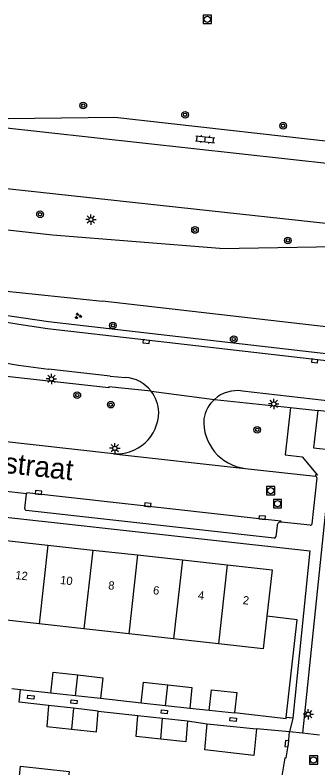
# Model space of a CAD drawing. Extents: x 132994 to 136000, y 393499 to 395512.
# Drawn here: x 133756.8 to 133793.3, y 394951.9 to 395042.7 of the extents above; entities that cross this region are included whole.
import ezdxf

# ---------------------------------------------------------------- set-up
doc = ezdxf.new("R2010")
doc.units = 0
for name, color, linetype in [('gg-afsc-hekwerk', 7, 'Continuous'), ('gg-anno-huisnummerreeks BGT', 7, 'Continuous'), ('gg-anno-openbare ruimte label', 7, 'Continuous'), ('gg-bbg-bijgebouw', 7, 'Continuous'), ('gg-bbg-hoofdgebouw', 7, 'Continuous'), ('gg-bbg-tussenscheiding', 7, 'Continuous'), ('gg-knt-verharding', 7, 'Continuous'), ('gg-knt-verharding nz', 7, 'Continuous'), ('gt-grn-groengrens', 7, 'Continuous'), ('gt-grn-vlakafsluiter', 7, 'Continuous'), ('gt-grn-weggrens', 7, 'Continuous'), ('gt-symb-boom', 7, 'Continuous'), ('gt-symb-groenvak', 7, 'Continuous'), ('gt-symb-klinker verharding', 7, 'Continuous'), ('gt-symb-kolk', 7, 'Continuous'), ('gt-symb-kolk center center', 7, 'Continuous'), ('gt-symb-lichtmast', 7, 'Continuous'), ('gt-symb-rioolschacht', 7, 'Continuous')]:
    doc.layers.add(name, color=color, linetype=linetype)

# ---------------------------------------------------------------- blocks, each defined once
blk = doc.blocks.new('gt0-RS')
at = {"layer": 'gt-symb-rioolschacht'}
blk.add_lwpolyline([(-0.5, -0.5), (0.5, -0.5), (0.5, 0.5), (-0.5, 0.5)], close=True, dxfattribs=at)
blk.add_circle((0, 0), 0.375, dxfattribs=at)
blk = doc.blocks.new('gt0-LMAST')
at = {"layer": 'gt-symb-lichtmast'}
for p, q in [((-0.182, 0.173), (-0.447, 0.438)), ((-0.005, 0.246), (-0.005, 0.621)), ((0.172, 0.173), (0.437, 0.438)), ((-0.255, -0.004), (-0.63, -0.004)), ((-0.182, -0.181), (-0.447, -0.446)), ((-0.005, -0.254), (-0.005, -0.629)), ((0.437, -0.446), (0.172, -0.181)), ((0.245, -0.004), (0.62, -0.004))]:
    blk.add_line(p, q, dxfattribs=at)
blk.add_circle((-0.005, -0.004), 0.25, dxfattribs=at)
blk = doc.blocks.new('gt0-KOLK')
at = {"layer": 'gt-symb-kolk'}
blk.add_lwpolyline([(0, 0), (0.375, 0), (0.375, 0.4), (-0.375, 0.4), (-0.375, 0), (0, 0)], dxfattribs=at)
blk = doc.blocks.new('gt0-BOOM')
at = {"layer": 'gt-symb-boom'}
for radius in [0.4, 0.2]:
    blk.add_circle((0, 0), radius, dxfattribs=at)
blk = doc.blocks.new('gt0-GRVAK')
at = {"layer": 'gt-symb-groenvak'}
for p, q in [((-0.11, 0.189), (-0.228, 0.24)), ((-0.182, 0.153), (0.088, 0.153)), ((-0.091, 0.211), (-0.156, 0.322)), ((-0.047, 0.214), (-0.047, 0.393)), ((-0.004, 0.211), (0.061, 0.322)), ((0.015, 0.189), (0.133, 0.24)), ((0.262, -0.052), (0.197, 0.059)), ((0.305, -0.049), (0.305, 0.13)), ((0.349, -0.052), (0.414, 0.059)), ((-0.245, -0.228), (-0.363, -0.177)), ((-0.318, -0.264), (-0.047, -0.264)), ((-0.226, -0.206), (-0.291, -0.095)), ((-0.183, -0.203), (-0.183, -0.024)), ((-0.139, -0.206), (-0.074, -0.095)), ((-0.12, -0.228), (-0.002, -0.177)), ((0.243, -0.074), (0.125, -0.023)), ((0.17, -0.11), (0.441, -0.11)), ((0.368, -0.074), (0.486, -0.023))]:
    blk.add_line(p, q, dxfattribs=at)
blk = doc.blocks.new('gt0-KL1')
at = {"layer": 'gt-symb-klinker verharding'}
for p, q in [((-1.15, 0.3), (1.15, 0.3)), ((-1, -0.3), (-1, 0.3)), ((-0.5, 0.3), (-0.5, 0.45)), ((0, -0.3), (0, 0.3)), ((0.5, 0.3), (0.5, 0.45)), ((1, -0.3), (1, 0.3)), ((-1.15, -0.3), (1.15, -0.3)), ((-0.5, -0.45), (-0.5, -0.3)), ((0.5, -0.45), (0.5, -0.3))]:
    blk.add_line(p, q, dxfattribs=at)
blk = doc.blocks.new('gt0-KOLKCC')
at = {"layer": 'gt-symb-kolk center center'}
blk.add_lwpolyline([(-0.375, 0.2), (0.375, 0.2), (0.375, -0.2), (-0.375, -0.2)], close=True, dxfattribs=at)

msp = doc.modelspace()

# ---------------------------------------------------------------- linework, layer by layer
at = {"layer": 'gg-afsc-hekwerk'}
for p, q in [((133768.094, 394997.721), (133706.131, 395004.561)), ((133757.449, 394961.312), (133756.412, 394961.429)), ((133761.084, 394960.902), (133757.449, 394961.312)), ((133771.992, 394959.686), (133767.081, 394960.24)), ((133780.187, 394958.794), (133777.829, 394959.048)), ((133766.821, 394958.743), (133771.583, 394958.214)), ((133789.305, 394953.107), (133786.435, 394936.039))]:
    msp.add_line(p, q, dxfattribs=at)
for points in [[(133789.47, 394957.983), (133790.782, 394969.763), (133787.138, 394970.172)], [(133783.223, 394958.554), (133789.456, 394957.851), (133789.47, 394957.983)]]:
    msp.add_lwpolyline(points, dxfattribs=at)
at = {"layer": 'gg-bbg-bijgebouw'}
for p, q in [((133764.082, 394960.571), (133761.084, 394960.902)), ((133767.081, 394960.24), (133764.082, 394960.571)), ((133763.828, 394959.077), (133760.834, 394959.412)), ((133766.821, 394958.743), (133763.828, 394959.077)), ((133774.911, 394959.367), (133771.992, 394959.686)), ((133777.829, 394959.048), (133774.911, 394959.367)), ((133771.583, 394958.214), (133774.572, 394957.885)), ((133774.572, 394957.885), (133777.561, 394957.556)), ((133779.948, 394957.191), (133785.898, 394956.577))]:
    msp.add_line(p, q, dxfattribs=at)
for points in [[(133761.084, 394960.902), (133761.363, 394963.426), (133764.362, 394963.095)], [(133764.362, 394963.095), (133767.36, 394962.765), (133767.081, 394960.24)], [(133771.992, 394959.686), (133772.267, 394962.211), (133775.186, 394961.892)], [(133775.186, 394961.892), (133778.105, 394961.573), (133777.829, 394959.048)], [(133780.187, 394958.794), (133780.458, 394961.319), (133783.497, 394960.992), (133783.223, 394958.554)], [(133760.834, 394959.412), (133760.613, 394956.888), (133763.601, 394956.557)], [(133763.601, 394956.557), (133766.588, 394956.226), (133766.821, 394958.743)], [(133774.372, 394955.356), (133771.386, 394955.684), (133771.583, 394958.214)], [(133783.223, 394958.554), (133783.213, 394958.469), (133780.187, 394958.794)], [(133777.561, 394957.556), (133777.358, 394955.027), (133774.372, 394955.356)], [(133785.898, 394956.577), (133785.564, 394953.392), (133779.67, 394954.052), (133779.948, 394957.191)]]:
    msp.add_lwpolyline(points, dxfattribs=at)
at = {"layer": 'gg-bbg-hoofdgebouw'}
for p, q in [((133755.35, 394979.357), (133760.753, 394978.761)), ((133760.753, 394978.761), (133766.156, 394978.164)), ((133766.156, 394978.164), (133771.558, 394977.568)), ((133771.558, 394977.568), (133776.961, 394976.971)), ((133776.961, 394976.971), (133782.364, 394976.375)), ((133759.692, 394969.266), (133754.291, 394969.866)), ((133765.094, 394968.665), (133759.692, 394969.266)), ((133770.495, 394968.065), (133765.094, 394968.665)), ((133775.897, 394967.465), (133770.495, 394968.065)), ((133781.298, 394966.864), (133775.897, 394967.465))]:
    msp.add_line(p, q, dxfattribs=at)
for points in [[(133782.364, 394976.375), (133787.767, 394975.778), (133787.138, 394970.172)], [(133787.138, 394970.172), (133786.7, 394966.264), (133781.298, 394966.864)], [(133757.199, 394949.706), (133757.466, 394952.097), (133763.298, 394951.444), (133763.075, 394949.456)]]:
    msp.add_lwpolyline(points, dxfattribs=at)
at = {"layer": 'gg-bbg-tussenscheiding'}
for p, q in [((133760.753, 394978.761), (133759.692, 394969.266)), ((133766.156, 394978.164), (133765.094, 394968.665)), ((133771.558, 394977.568), (133770.495, 394968.065)), ((133776.961, 394976.971), (133775.897, 394967.465)), ((133782.364, 394976.375), (133781.298, 394966.864)), ((133764.082, 394960.571), (133764.362, 394963.095)), ((133774.911, 394959.367), (133775.186, 394961.892)), ((133763.828, 394959.077), (133763.601, 394956.557)), ((133774.372, 394955.356), (133774.572, 394957.885))]:
    msp.add_line(p, q, dxfattribs=at)
at = {"layer": 'gg-knt-verharding'}
for p, q in [((133822.979, 395021.635), (133746.282, 395030.078)), ((133781.477, 395014.524), (133795.502, 395014.768)), ((133768.254, 394999.147), (133760.828, 395000)), ((133768.254, 394999.147), (133770.091, 394998.976)), ((133800.526, 394995.439), (133784.178, 394997.345)), ((133768.645, 394989.771), (133708.52, 394996.435)), ((133780.821, 394996.341), (133789.963, 394995.364)), ((133799.515, 394994.268), (133793.265, 394994.982)), ((133784.51, 394988.018), (133792.966, 394987.071)), ((133793.139, 394986.857), (133792.564, 394981.339)), ((133758.184, 394984.955), (133755.39, 394985.252)), ((133757.984, 394983.175), (133758.184, 394984.955)), ((133788.003, 394979.587), (133758.148, 394982.95)), ((133788.356, 394981.118), (133788.213, 394979.76)), ((133792.341, 394981.152), (133788.835, 394981.526)), ((133790.263, 394957.895), (133789.47, 394957.983)), ((133789.856, 394956.224), (133785.898, 394956.577)), ((133791.413, 394956.085), (133789.856, 394956.224)), ((133793.45, 394955.847), (133791.413, 394956.085))]:
    msp.add_line(p, q, dxfattribs=at)
for points in [[(133822.979, 395021.635), (133799.512, 395026.89), (133768.813, 395030.34), (133746.282, 395030.078)], [(133874.225, 395008.567), (133868.836, 395009.122), (133845.49, 395011.838), (133822.318, 395014.495), (133750.599, 395022.315), (133724.94, 395025.159), (133706.97, 395027.168), (133704.01, 395027.246), (133686.896, 395026.871)], [(133781.477, 395014.524), (133761.294, 395016.152), (133739.879, 395018.515), (133712.712, 395021.56), (133689.496, 395024.11), (133686.631, 395024.429)], [(133685.853, 395017.266), (133710.428, 395014.444), (133733.641, 395011.92), (133754.939, 395009.49), (133767.315, 395008.188)], [(133803.009, 395000), (133772.607, 395003.5), (133760.688, 395004.836), (133757.228, 395005.351), (133735.229, 395009.073), (133733.476, 395009.301)], [(133838.166, 395000), (133819.405, 395002.212), (133767.315, 395008.188)], [(133732.946, 395004.495), (133736.017, 395004.08), (133757.188, 395000.47), (133760.828, 395000)], [(133773.184, 394997.342), (133768.107, 394997.851), (133768.094, 394997.721)], [(133789.963, 394995.364), (133789.323, 394989.649), (133791.373, 394989.418), (133793.245, 394987.196), (133792.989, 394987.236), (133792.966, 394987.071)], [(133793.265, 394994.982), (133792.755, 394990.502), (133794.936, 394990.265), (133791.413, 394956.085)], [(133714.307, 394986.713), (133792.304, 394978.081), (133790.263, 394957.895)], [(133760.834, 394959.412), (133757.285, 394959.808), (133757.449, 394961.312)], [(133789.305, 394953.107), (133789.459, 394953.079), (133789.728, 394954.784), (133789.856, 394956.224)]]:
    msp.add_lwpolyline(points, dxfattribs=at)
for centre, radius, start, end in [((133769.803, 394994.687), 4.298, 38.14203, 86.16391), ((133769.805, 394994.692), 4.294, 1.278, 38.10354), ((133783.553, 394993.319), 4.074, 81.18251, 132.11887), ((133783.557, 394993.322), 4.074, 132.17852, 170.60056), ((133769.017, 394994.839), 5.081, 265.80054, 359.43031), ((133785.177, 394993.63), 5.651, 176.37304, 263.22488), ((133792.947, 394986.878), 0.194, 353.66806, 84.23686), ((133758.175, 394983.142), 0.193, 170.07473, 262.10106), ((133788.788, 394981.096), 0.432, 83.72909, 177.11793), ((133792.362, 394981.353), 0.203, 264.0557, 355.90834), ((133787.988, 394979.82), 0.233, 273.79042, 345.17362)]:
    msp.add_arc(centre, radius, start, end, dxfattribs=at)
at = {"layer": 'gg-knt-verharding nz'}
msp.add_lwpolyline([(133788.835, 394981.526), (133788.847, 394981.637), (133786.541, 394981.873), (133758.201, 394985.062), (133758.184, 394984.955)], dxfattribs=at)
at = {"layer": 'gt-grn-groengrens'}
msp.add_lwpolyline([(133568.55, 395027.016), (133598.605, 395024.265), (133629.508, 395021.349), (133654.602, 395018.736), (133699.62, 395013.815), (133719.54, 395011.607), (133729.257, 395010.661), (133736.756, 395009.518), (133740.544, 395009.001), (133753.397, 395006.823), (133760.835, 395005.738), (133823.139, 394998.553), (133826.998, 394998.206), (133842.575, 394996.032), (133846.453, 394995.188)], dxfattribs=at)
at = {"layer": 'gt-grn-vlakafsluiter'}
msp.add_line((133777.561, 394957.556), (133779.948, 394957.191), dxfattribs=at)
at = {"layer": 'gt-grn-weggrens'}
for p, q in [((133773.184, 394997.342), (133780.821, 394996.341)), ((133789.963, 394995.364), (133793.265, 394994.982)), ((133768.645, 394989.771), (133784.51, 394988.018)), ((133790.263, 394957.895), (133789.856, 394956.224))]:
    msp.add_line(p, q, dxfattribs=at)

# ---------------------------------------------------------------- block references
at = {"layer": 'gt-symb-boom'}
for p in [(133765.01, 395031.785), (133777.268, 395030.664), (133789.087, 395029.349), (133759.802, 395018.664), (133778.468, 395016.776), (133789.663, 395015.51), (133768.582, 395005.259), (133783.132, 395003.604), (133764.287, 394996.854), (133768.32, 394995.698), (133785.969, 394992.67)]:
    msp.add_blockref('gt0-BOOM', p, dxfattribs=at)
at = {"layer": 'gt-symb-groenvak'}
msp.add_blockref('gt0-GRVAK', (133764.38, 395006.39), dxfattribs=at)
at = {"layer": 'gt-symb-klinker verharding', "rotation": -5.739098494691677}
msp.add_blockref('gt0-KL1', (133779.698, 395027.711), dxfattribs=at)
at = {"layer": 'gt-symb-kolk'}
for p, rotation in [((133772.607, 395003.5), 173.6281775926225), ((133792.905, 395001.168), 173.45090842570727), ((133759.585, 394984.911), -6.4373318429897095), ((133772.751, 394983.426), -6.429312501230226), ((133786.541, 394981.873), -5.844692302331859), ((133789.728, 394954.784), 84.9012794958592)]:
    msp.add_blockref('gt0-KOLK', p, dxfattribs=dict(at, rotation=rotation))
at = {"layer": 'gt-symb-kolk center center'}
for p, rotation in [((133758.695, 394960.423), -6.291176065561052), ((133763.892, 394959.849), 173.70882393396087), ((133774.774, 394958.636), 173.64376650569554), ((133783.058, 394957.726), 173.73377044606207)]:
    msp.add_blockref('gt0-KOLKCC', p, dxfattribs=dict(at, rotation=rotation))
at = {"layer": 'gt-symb-lichtmast'}
for p in [(133765.935, 395018.03), (133761.183, 394998.807), (133787.964, 394995.787), (133768.818, 394990.437), (133792.116, 394958.358)]:
    msp.add_blockref('gt0-LMAST', p, dxfattribs=at)
at = {"layer": 'gt-symb-rioolschacht', "rotation": -90.51564809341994}
msp.add_blockref('gt0-RS', (133779.965, 395042.193), dxfattribs=at)
at = {"layer": 'gt-symb-rioolschacht'}
for p in [(133787.584, 394985.316), (133788.408, 394983.754), (133792.748, 394952.828)]:
    msp.add_blockref('gt0-RS', p, dxfattribs=at)

# ---------------------------------------------------------------- texts
at = {"layer": 'gg-anno-huisnummerreeks BGT'}
for s, p in [('12', (133756.786, 394974.671)), ('10', (133762.188, 394974.075)), ('8', (133767.977, 394973.436)), ('6', (133773.379, 394972.84)), ('4', (133778.783, 394972.243)), ('2', (133784.185, 394971.647))]:
    msp.add_text(s, height=1, rotation=353.7, dxfattribs=at).set_placement(p)
at = {"layer": 'gg-anno-openbare ruimte label'}
msp.add_text('Harzstraat', height=2.5, rotation=353.7, dxfattribs=at).set_placement((133748.335, 394988.262))

doc.saveas('drawing.dxf')
